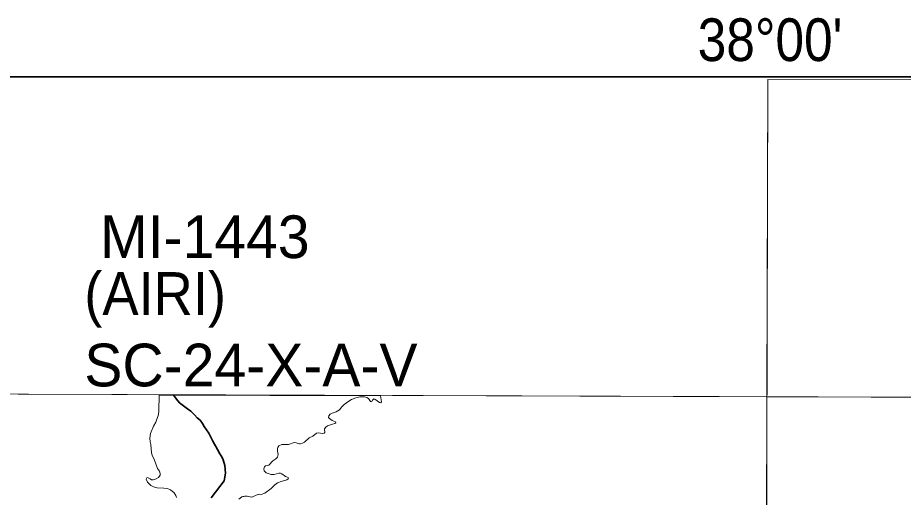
# Model space of a CAD drawing. Extents: x 553962 to 842807, y 8883888 to 9032388.
# Drawn here: x 576874 to 587242, y 8919850 to 8925463 of the extents above; entities that cross this region are included whole.
import ezdxf
from ezdxf.enums import TextEntityAlignment as Align

# ---------------------------------------------------------------- set-up
doc = ezdxf.new("R2010")
doc.units = 0
doc.header["$LTSCALE"] = 200
doc.linetypes.add('LONG_DASH_SHORT_DASH', pattern=[9.9, 6, -1.2, 1.5, -1.2])
doc.layers.add('6', color=7, linetype='Continuous', lineweight=13)

msp = doc.modelspace()

# ---------------------------------------------------------------- linework, layer by layer
at = {"layer": '6'}
msp.add_line((581121.2, 8921038.8), (578531.5, 8921044.3), dxfattribs=at)
at = {"layer": '6', "lineweight": 35}
msp.add_lwpolyline([(574695.3, 8924769.6), (626625.7, 8924769.6), (626625.7, 8896026.7), (574695.3, 8896026.7)], close=True, dxfattribs=at)
at = {"layer": '6'}
for points in [[(585656.3, 8924738.8), (585614.8, 8909969.8), (585573.6, 8896026.7)], [(574684.9, 8921064.7), (596639.8, 8920989.8), (607636.3, 8920937.2), (626625.7, 8920820.5)], [(578531.5, 8921044.3), (578525.4, 8920861.1), (578521, 8920819.7), (578490.8, 8920729.8), (578464.8, 8920681.3), (578427.7, 8920597.6), (578420.3, 8920542.1), (578424.2, 8920499.8), (578432.8, 8920469.4), (578439.3, 8920370.1), (578446.7, 8920342.4), (578476.9, 8920285.4), (578512.4, 8920187.2), (578534, 8920155.6), (578541.8, 8920127.9), (578541.8, 8920108.5), (578520.6, 8920080.8), (578496, 8920066.1), (578459.8, 8920053.6), (578441.4, 8920053.6), (578423.4, 8920067.4), (578392.2, 8920079.5), (578384, 8920077.7), (578378.4, 8920063.1), (578394.4, 8920026.8), (578431.9, 8919986.2), (578483, 8919962.8), (578507.1, 8919958.9), (578585.1, 8919958), (578628.8, 8919952.9), (578664.6, 8919935.5), (578704.8, 8919902.2), (578724.3, 8919870.2), (578732, 8919846.5)], [(579461, 8919829.2), (579499, 8919853.4), (579510.9, 8919857.7), (579520.2, 8919857.3), (579532.2, 8919862.4), (579560.4, 8919862.5), (579574.2, 8919857.3), (579615.3, 8919851.7), (579664.7, 8919876.3), (579702.2, 8919884.9), (579725.6, 8919882.8), (579767.1, 8919897.1), (579839.7, 8919952.8), (579883, 8919994.7), (579914.9, 8920018.5), (579956.5, 8920036.3), (580025.6, 8920054.4), (580039.4, 8920065.7), (580043.3, 8920072.7), (580039.4, 8920083), (580010, 8920094.7), (579966.9, 8920124.4), (579951.3, 8920131.8), (579930.5, 8920133.6), (579875.2, 8920117.1), (579840.6, 8920115.8), (579783.6, 8920134.8), (579758.8, 8920158.4), (579754.6, 8920184.2), (579761.9, 8920206.2), (579774.5, 8920217), (579813.8, 8920225.3), (579860.1, 8920275.4), (579895.5, 8920300.4), (579913.9, 8920318.8), (579921.6, 8920350.7), (579915.8, 8920390.8), (579915.4, 8920422), (579918, 8920433.2), (579931, 8920453.1), (579965, 8920468.6), (580042.9, 8920468.2), (580110.4, 8920489.4), (580135, 8920486.7), (580169.2, 8920474.7), (580182.1, 8920474.7), (580209.9, 8920482.9), (580232.8, 8920495.5), (580286.8, 8920543.9), (580330.1, 8920563.4), (580370.3, 8920600.1), (580392.2, 8920604), (580447.8, 8920597.7), (580462.7, 8920600.1), (580468.1, 8920609.3), (580465.4, 8920649.4), (580481.8, 8920671.8), (580500.4, 8920686.3), (580558.2, 8920706.8), (580587.8, 8920713.2), (580598.4, 8920722.8), (580593.6, 8920732.5), (580556.5, 8920749.3), (580522.5, 8920773), (580513.8, 8920785.1), (580515.5, 8920802.9), (580532.8, 8920821), (580553.6, 8920834), (580604.1, 8920848.2), (580639.6, 8920872.9), (580666.9, 8920910.2), (580696.6, 8920937.3), (580749.4, 8920976.7), (580780.5, 8920993.1), (580834, 8921014.6), (580880.7, 8921023.8), (580934, 8921026.4), (580962.9, 8921016.4), (580979.4, 8921004.4), (581002.3, 8920972.3), (581011.8, 8920966.3), (581020.4, 8920969.7), (581025.8, 8920985.4), (581044.8, 8921001.3), (581055.1, 8920999.5), (581110, 8920959.3), (581125.1, 8920955.5), (581132, 8920968.4), (581121.2, 8921038.8)]]:
    msp.add_lwpolyline(points, dxfattribs=at)
for points in [[(585656.3, 8924738.8), (596655.5, 8924715.8), (596639.8, 8920989.8), (585645.8, 8921027.3)], [(585645.8, 8921027.3), (574684.9, 8921064.7), (574653.9, 8910009.3), (585614.8, 8909969.8)]]:
    msp.add_lwpolyline(points, close=True, dxfattribs=at)
at = {"layer": '6', "linetype": 'LONG_DASH_SHORT_DASH', "lineweight": 35}
msp.add_lwpolyline([(578702.1, 8921041.7), (578732.5, 8920996.5), (578770, 8920953.4), (578860.1, 8920883.7), (578900.2, 8920859.1), (578930.9, 8920824.9), (578945.6, 8920814.5), (578976.3, 8920780.8), (579009.1, 8920751.4), (579036, 8920715.1), (579057.2, 8920678.8), (579111.6, 8920601.8), (579159.6, 8920505), (579214.2, 8920410.6), (579239.6, 8920358), (579263.4, 8920321.7), (579278.1, 8920289.2), (579298, 8920220.5), (579306.6, 8920132.3), (579291, 8920043.1), (579137.8, 8919842.8)], dxfattribs=at)

# ---------------------------------------------------------------- texts
at = {"layer": '6', "width": 0.9}
msp.add_text("38°00'", height=500, dxfattribs=at).set_placement((585681.9, 8924955.9), align=Align.CENTER)
at = {"layer": '6'}
for s, p in [('MI-1443', (577838.3, 8922649.4)), ('SC-24-X-A-V', (577653.9, 8921147.9))]:
    msp.add_text(s, height=500, dxfattribs=at).set_placement(p)
at = {"layer": '6', "width": 0.95}
msp.add_text('(AIRI)', height=500, dxfattribs=at).set_placement((577653.9, 8921984.9))

doc.saveas('drawing.dxf')
